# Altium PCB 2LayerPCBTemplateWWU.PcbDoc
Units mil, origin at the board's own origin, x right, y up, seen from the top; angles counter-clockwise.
Board outline 4800 x 1750 mil, 2 copper layers (Top Layer, Bottom Layer); 87 components, 55 nets, 244 pads, 65 vias.
Unrouted connection lines stored in the file: 2.
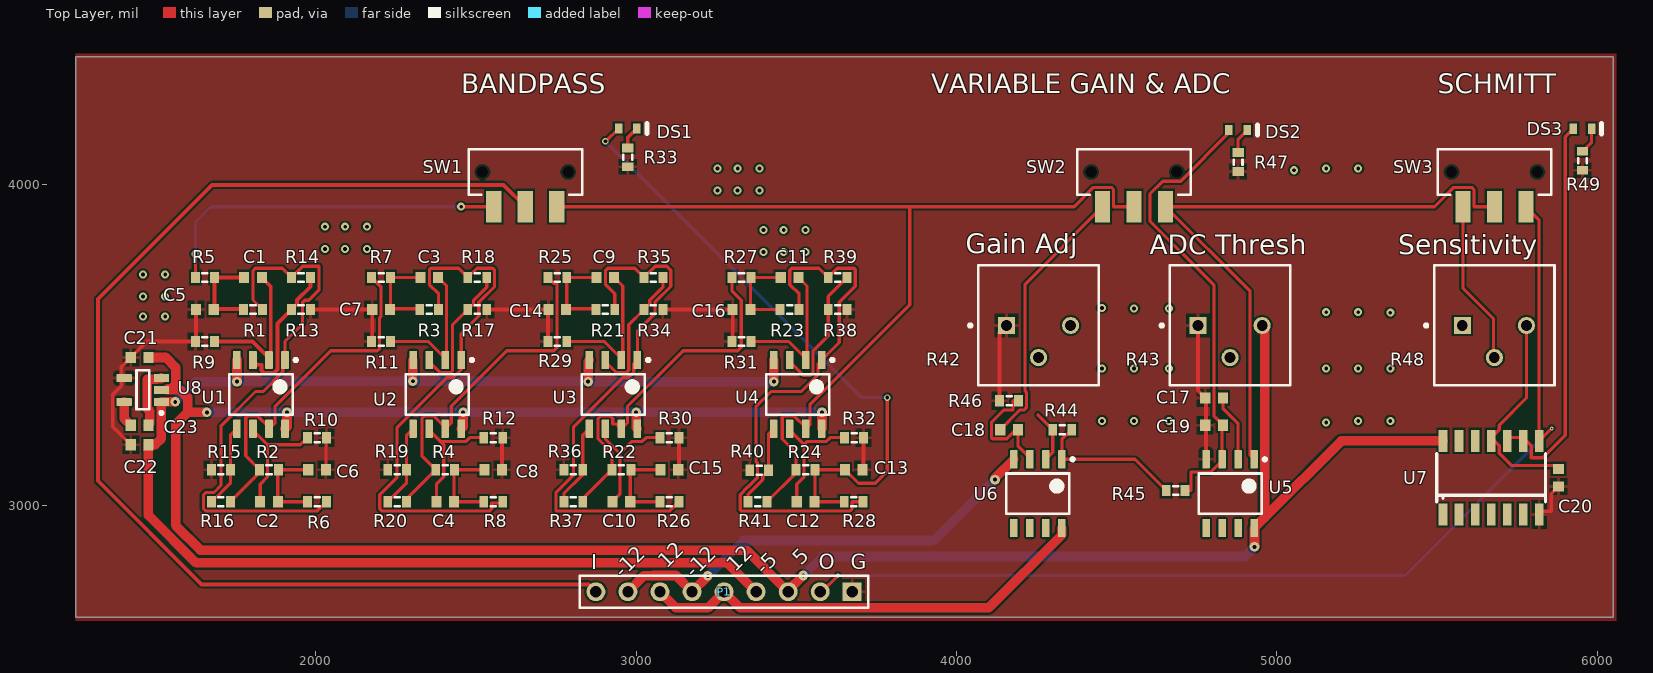
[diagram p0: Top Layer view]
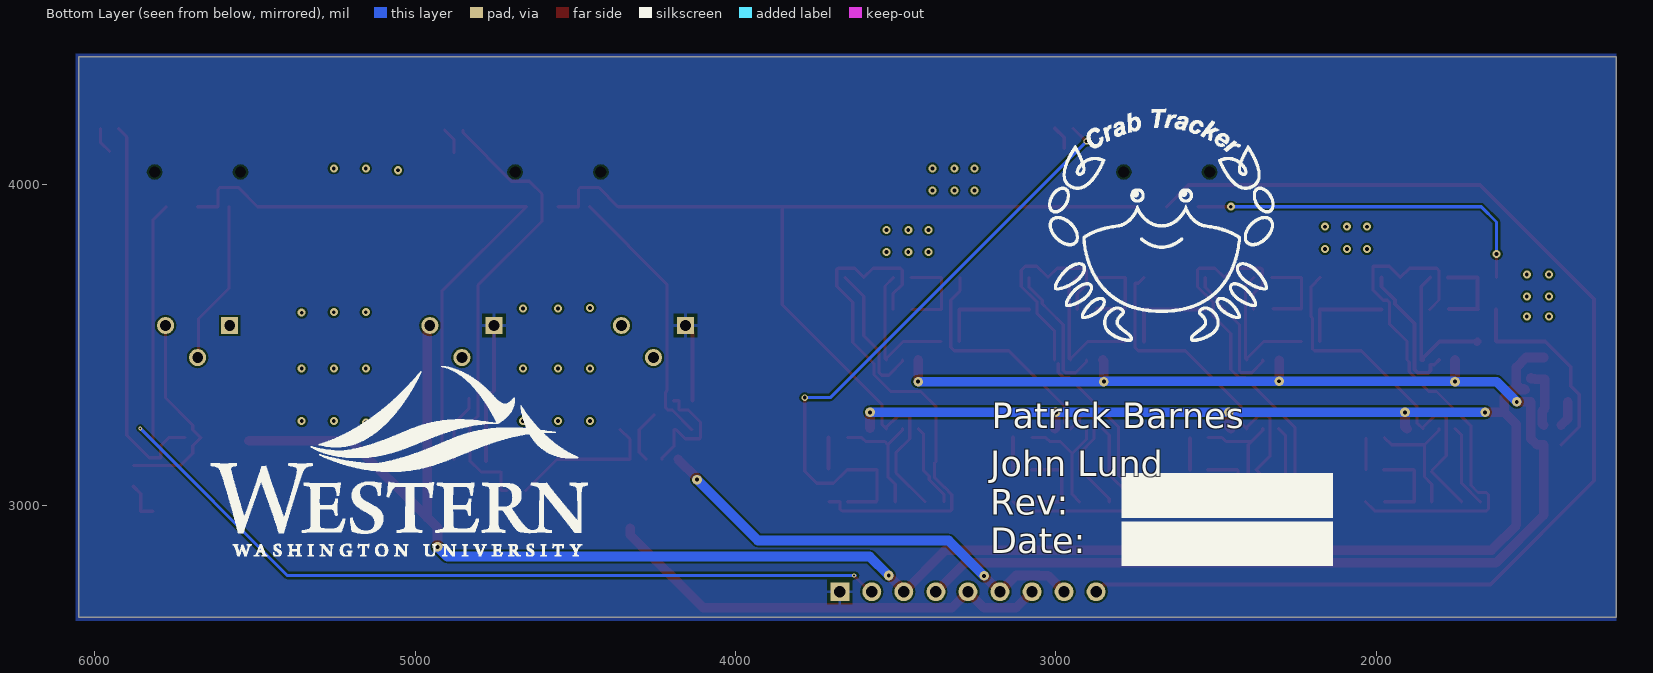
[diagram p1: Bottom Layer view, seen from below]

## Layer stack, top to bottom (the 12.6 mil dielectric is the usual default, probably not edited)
Top Solder: solder mask 0.4, Solder Resist, Dk 3.5
Top Layer: signal copper 1.4
Dielectric 1: dielectric 12.6, FR-4, Dk 4.8
Bottom Layer: signal copper 1.4
Bottom Solder: solder mask 0.4, Solder Resist, Dk 3.5

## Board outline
1250,2650 6050,2650 6050,4400 1250,4400

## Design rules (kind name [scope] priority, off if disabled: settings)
Clearance [All] p1: gap=6 ignorepadtopadclearanceinfootprint=FALSE except(0: Arc-Hole Track-Hole SMDPad-Hole THPad-Hole Via-Hole Fill-Hole Poly-Hole Region-Hole Text-Hole)
HoleSize [All] p1: absolutevalues=TRUE maxlimit=125 minlimit=13 maxpercent=80.000 minpercent=20.000
MinimumSolderMaskSliver [All] p1: minsoldermaskwidth=1
PasteMaskExpansion [All] p1: expansion=-2
PolygonConnect [All] p1: connectstyle=Relief reliefconductorwidth=10 reliefentries=4 polygonreliefangle="90 Angle" airgapwidth=10
RoutingVias [All] p1: holewidth=13 width=20 viastyle="Through Hole" minholewidth=13 minwidth=20 maxholewidth=125 maxwidth=250
SilkToSilkClearance [All] p1: silktosilkclearance=4
SilkToSolderMaskClearance [IsPad] p1: minsilkscreentomaskgap=6 clearancetoexposedcopper=TRUE
SolderMaskExpansion [All] p1: expansion=4
Width [All] p1: maxlimit=500 minlimit=6 preferedwidth=25
25 further rules are at their usual default settings.

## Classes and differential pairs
component class SchmittTrigger: C20 DS3 R48 R49 SW3 U7
component class BandpassFilter: C1 C2 C3 C4 C5 C6 C7 C8 C9 C10 C11 C12 C13 C14 C15 C16 C21 C22 C23 DS1 P1 R1 R2 R3 R4 R5 R6 R7 R8 R9 R10 R11 R12 R13 R14 R15 R16 R17 R18 R19 R20 R21 R22 R23 R24 R25 R26 R27 R28 R29 R30 R31 R32 R33 R34 R35 R36 R37 R38 R39 R40 R41 SW1 U1 U2 U3 U4 U8
component class ADC: C17 C18 C19 DS2 R42 R43 R44 R45 R46 R47 SW2 U5 U6

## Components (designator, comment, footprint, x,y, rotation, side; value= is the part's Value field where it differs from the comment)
C1 "Cap Semi" 1608[0603] 1803.91,3711.04 r0 top value=10nF
C2 "Cap Semi" 1608[0603] 1853.91,3011.04 r180 top value=10nF
C3 "Cap Semi" 1608[0603] 2353.91,3711.04 r0 top value=10nF
C4 "Cap Semi" 1608[0603] 2403.91,3011.04 r180 top value=10nF
C5 "Cap Semi" 1608[0603] 1653.91,3611.04 r0 top value=10nF
C6 "Cap Semi" 1608[0603] 2003.91,3111.04 r180 top value=10nF
C7 "Cap Semi" 1608[0603] 2203.91,3611.04 r0 top value=10nF
C8 "Cap Semi" 1608[0603] 2553.91,3111.04 r180 top value=10nF
C9 "Cap Semi" 1608[0603] 2903.91,3711.04 r0 top value=10nF
C10 "Cap Semi" 1608[0603] 2953.91,3011.04 r180 top value=10nF
C11 "Cap Semi" 1608[0603] 3478.91,3711.04 r0 top value=10nF
C12 "Cap Semi" 1608[0603] 3528.91,3011.04 r180 top value=10nF
C13 "Cap Semi" 1608[0603] 3678.91,3111.04 r180 top value=10nF
C14 "Cap Semi" 1608[0603] 2753.91,3611.04 r0 top value=10nF
C15 "Cap Semi" 1608[0603] 3103.91,3111.04 r180 top value=10nF
C16 "Cap Semi" 1608[0603] 3328.91,3611.04 r0 top value=10nF
C17 "Cap Semi" 1608[0603] 4803.91,3334.82 r180 top value=1uF
C18 "Cap Semi" 1608[0603] 4163.91,3236.04 r0 top value=0.1uF
C19 "Cap Semi" 1608[0603] 4803.91,3250.04 r0 top value=10nF
C20 "Cap Semi" 1608[0603] 5878.91,3086.04 r270 top value=10nF
C21 "Cap Semi" 1608[0603] 1450,3461.04 r0 top value=1uF
C22 "Cap Semi" 1608[0603] 1450,3188.77 r0 top value=1uF
C23 "Cap Semi" 1608[0603] 1450,3250 r0 top value=1uF
DS1 "TLMS1100-GS08" VISH-TLMX1100_V 2973.91,4176.04 r0 top
DS2 "TLMS1100-GS08" VISH-TLMX1100_V 4878.91,4171.04 r0 top
DS3 "TLMS1100-GS08" VISH-TLMX1100_V 5953.91,4175.17 r0 top
P1 "Header 9" HDR1X9 3674.38,2730 r180 top
R1 "Res3" J1-0603 1803.91,3611.04 r0 top value=220
R2 "Res3" J1-0603 1853.91,3111.04 r180 top value=220
R3 "Res3" J1-0603 2353.91,3611.04 r0 top value=220
R4 "Res3" J1-0603 2403.91,3111.04 r180 top value=220
R5 "Res3" J1-0603 1653.91,3711.04 r0 top value=100k
R6 "Res3" J1-0603 2003.91,3011.04 r180 top value=68k
R7 "Res3" J1-0603 2203.91,3711.04 r0 top value=100k
R8 "Res3" J1-0603 2553.91,3011.04 r180 top value=68k
R9 "Res3" J1-0603 1653.91,3511.04 r0 top value=330
R10 "Res3" J1-0603 2003.91,3211.04 r180 top value=330
R11 "Res3" J1-0603 2203.91,3511.04 r0 top value=330
R12 "Res3" J1-0603 2553.91,3211.04 r180 top value=330
R13 "Res3" J1-0603 1953.91,3611.04 r180 top value=470
R14 "Res3" J1-0603 1953.91,3711.04 r180 top value=1k
R15 "Res3" J1-0603 1703.91,3111.04 r0 top value=1k
R16 "Res3" J1-0603 1703.91,3011.04 r0 top value=1k
R17 "Res3" J1-0603 2503.91,3611.04 r180 top value=470
R18 "Res3" J1-0603 2503.91,3711.04 r180 top value=1k
R19 "Res3" J1-0603 2253.91,3111.04 r0 top value=1k
R20 "Res3" J1-0603 2253.91,3011.04 r0 top value=1k
R21 "Res3" J1-0603 2903.91,3611.04 r0 top value=220
R22 "Res3" J1-0603 2953.91,3111.04 r180 top value=220
R23 "Res3" J1-0603 3478.91,3611.04 r0 top value=220
R24 "Res3" J1-0603 3528.91,3111.04 r180 top value=220
R25 "Res3" J1-0603 2753.91,3711.04 r0 top value=100k
R26 "Res3" J1-0603 3103.91,3011.04 r180 top value=68k
R27 "Res3" J1-0603 3328.91,3711.04 r0 top value=100k
R28 "Res3" J1-0603 3678.91,3011.04 r180 top value=68k
R29 "Res3" J1-0603 2753.91,3511.04 r0 top value=330
R30 "Res3" J1-0603 3103.91,3211.04 r180 top value=330
R31 "Res3" J1-0603 3328.91,3511.04 r0 top value=330
R32 "Res3" J1-0603 3680.19,3211.04 r180 top value=330
R33 "Res3" J1-0603 2973.91,4086.04 r90 top value=1K
R34 "Res3" J1-0603 3053.91,3611.04 r180 top value=470
R35 "Res3" J1-0603 3053.91,3711.04 r180 top value=1k
R36 "Res3" J1-0603 2803.91,3111.04 r0 top value=1k
R37 "Res3" J1-0603 2803.91,3011.04 r0 top value=1k
R38 "Res3" J1-0603 3628.91,3611.04 r180 top value=470
R39 "Res3" J1-0603 3628.91,3711.04 r180 top value=1k
R40 "Res3" J1-0603 3383.91,3109.07 r0 top value=1k
R41 "Res3" J1-0603 3378.91,3011.04 r0 top value=1k
R42 "3386P-1-104LF" BOUR-3386P 4256.03,3511.04 r0 top
R43 "3386P-1-104LF" BOUR-3386P 4853.91,3511.04 r0 top
R44 "Res3" J1-0603 4330.05,3236.04 r180 top value=20k
R45 "Res3" J1-0603 4683.91,3046.04 r0 top value=5k
R46 "Res3" J1-0603 4163.91,3326.04 r0 top value=1M
R47 "Res3" J1-0603 4878.91,4071.04 r90 top value=1k
R48 "3386P-1-104LF" BOUR-3386P 5678.91,3511.04 r0 top
R49 "Res3" J1-0603 5953.91,4075.17 r270 top value=1k
SW1 "JS102011SAQN" CKCP-JS102011SAQN-3_V 2653.91,3986.04 r180 top
SW2 "JS102011SAQN" CKCP-JS102011SAQN-3_V 4553.91,3986.04 r180 top
SW3 "JS102011SAQN" CKCP-JS102011SAQN-3_V 5678.91,3986.04 r180 top
U1 "OPA2171AIDR" D0008A_N 1828.91,3346.04 r270 top
U2 "OPA2171AIDR" D0008A_N 2378.91,3346.04 r270 top
U3 "OPA2171AIDR" D0008A_N 2928.91,3346.04 r270 top
U4 "OPA2171AIDR" D0008A_N 3503.91,3346.04 r270 top
U5 "OPA2171AIDR" D0008A_N 4853.91,3036.04 r270 top
U6 "OPA2171AIDR" D0008A_N 4253.91,3036.04 r270 top
U7 "74HC14D HEX INV" 14-SOIC 5668.91,3086.04 r0 top
U8 "TPS60403DBVR" DBV0005A_M 1460,3360 r180 top

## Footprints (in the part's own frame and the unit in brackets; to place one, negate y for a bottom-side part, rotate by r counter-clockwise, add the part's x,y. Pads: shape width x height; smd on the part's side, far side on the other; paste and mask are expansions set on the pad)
14-SOIC [mm] "14-SOIC 74HC14"
  rect 0.7x1.75 smd: 1(-3.81,-2.921) 2(-2.54,-2.921) 3(-1.27,-2.921) 4(0,-2.921) 5(1.27,-2.921) 6(2.54,-2.921) 7(3.81,-2.921) 8(3.81,2.921) 9(2.54,2.921) 10(1.27,2.921) 11(0,2.921) 12(-1.27,2.921) 13(-2.54,2.921) 14(-3.81,2.921)
  silkscreen extent -4.32,-1.91 4.32,1.91, body extent -4.32,-2.92 4.32,2.92, height 1.6
1608[0603] [mm] "Chip Capacitor, Body 1.6x0.8mm, IPC High Density"
  rect 0.8x0.9 smd: 1(-0.7,0) 2(0.7,0)
  body extent -0.87,-0.48 0.87,0.48, height 1.3
BOUR-3386P [mm] "THD, 3-Leads, Body 9.53x9.53mm, Pitch 2.54mm"
  rect 1.35x1.35 hole 0.85: 1(-2.54,1.27)
  round 1.35 hole 0.85: 2(0,-1.27) 3(2.54,1.27)
  silkscreen extent -5.54,-3.48 4.76,6.05, body extent -4.79,-3.52 4.79,6.06, height 4.95
CKCP-JS102011SAQN-3_V [mm] "SMD, 3-Leads, Body 9x3.6mm, Pitch 2.5mm"
  rect 1.2x2.5 smd: 1(-2.5,1.375) 2(0,1.375) 3(2.5,1.375)
  round 0.6 hole 0.9 unplated: MH1(-3.4,-1.375) MH2(3.4,-1.375)
  silkscreen extent -4.5,-3.17 4.5,0.43, body extent -4.5,-5.18 4.5,2.37, height 3.52
D0008A_N [mm] "SOIC, 8-Leads, Body 5x4mm, Pitch 1.27mm, IPC Medium Density"
  rrect17% 1.45x0.6 smd: 1(-2.725,1.905) 2(-2.725,0.635) 3(-2.725,-0.635) 4(-2.725,-1.905) 5(2.725,-1.905) 6(2.725,-0.635) 7(2.725,0.635) 8(2.725,1.905)
  silkscreen extent -2.85,-2.5 1.6,2.88, body extent -3,-2.45 3,2.45, height 1.63
DBV0005A_M [mm] "SOT23, 5-Leads, Body 3.05x1.75mm, Pitch 0.95mm, IPC Low Density"
  rrect15% 1.2x0.65 smd: 1(-1.475,0.95) 2(-1.475,0) 3(-1.475,-0.95) 4(1.475,-0.95) 5(1.475,0.95)
  silkscreen extent -1.6,-1.55 0.5,1.95, body extent -1.42,-1.46 1.42,1.46, height 1.08
HDR1X9 [mm] "Connector; Header; 9 Position"
  rect 1.5x1.5 hole 0.9: 1(0,0)
  round 1.5 hole 0.9: 2(2.54,0) 3(5.08,0) 4(7.62,0) 5(10.16,0) 6(12.7,0) 7(15.24,0) 8(17.78,0) 9(20.32,0)
  silkscreen extent -1.27,-1.27 21.59,1.27
J1-0603 [mm] "Chip Resistor, Body 1.6x0.8mm, IPC High Density"
  rect 0.7x0.9 smd: 1(-0.75,0) 2(0.75,0)
  silkscreen extent -0.2,-0.35 0.2,0.35, body extent -0.85,-0.48 0.85,0.48, height 0.9
VISH-TLMX1100_V [mm] "SMD, 2-Leads, Body 1.6x0.8mm"
  rect 0.6x0.8 smd: 1(-0.725,0) 2(0.725,0)
  silkscreen extent 1.53,-0.4 1.53,0.4, body extent -0.8,-0.4 0.8,0.4, height 0.65

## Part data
C1 C2 C3 C4 C5 C6 C7 C8 C9 C10 C11 C12 C13 C14 C15 C16 C17 C18 C19 C20 C21 C22 C23: "Capacitor (Semiconductor SIM Model)"
DS1 DS2 DS3: library part CMP-1666-00027-1, "LED, RED, 2.1 V, -40 to 100 degC, 2-Pin SMD (0603), RoHS, Tape and Reel", Capacitance="12 pF", Case/Package=0603, Case Code (Metric)=1608, Max Operating Temperature=125degC, Min Operating Temperature=-55degC, Package Quantity=4000, Resistance="100000000000 Ohm", Tolerance=5%, Type (Capacitors)=C0G, Voltage Rating="50 V"
P1: "Header, 9-Pin"
R1 R2 R3 R4 R5 R6 R7 R8 R9 R10 R11 R12 R13 R14 R15 R16 R17 R18 R19 R20 R21 R22 R23 R24 R25 R26 R27 R28 R29 R30 R31 R32 R33 R34 R35 R36 R37 R38 R39 R40 R41 R44 R45 R46 R47 R49: "Resistor"
R42 R43 R48: library part CMP-2000-05592-1, "Square Trimpot(R) Trimming Potentiometer, 100 KOhm, +/- 10%, 0.5 W, -55 to 125 degC, 3-Pin THD, RoHS, Tube", Manufacturer=Bourns, Manufacturer Series=3386, Maximum Operating Temperature=125C, Minimum Operating Temperature=-55C, Operating Temperature-Max (Cel)=125, Operating Temperature-Min (Cel)=-55, Package=RectangularPackage, Package Description="3-Pin Through Hole Device, Body 9.53 x 9.53 mm, Pitch 2.54 mm", Package Reference=3386P, Power Rating=1/2W, Rated Power Dissipation (P) (W)=0.5, Rated Temperature (Cel)=85, Resistance (ohm)=100000, Resistance Law=Linear, Resistance Value=100KOhm, Resistive Element Material=Cermet, Temperature Coefficient=100ppm/C, Tolerance=10%, Tolerance (%)=10
SW1 SW2 SW3: library part CMP-2000-06501-1, "Sub-Miniature Slide Switch, SPDT, -40 to 85 degC, 3-Pin SMD, RoHS, Tape and Reel", Actuator Color=Black, Contact Rating @ Voltage=0.3@6VDCA, Dielectric Strength=500VAC, Manufacturer="C&K Components", Maximum AC Voltage Rating=N/A, Maximum Contact Resistance=70mOhm, Maximum DC Voltage Rating=6V, Minimum Insulation Resistance=100MOhm, Operating Temperature=-40to85C, Package Description="3-Pin Surface Mount Device, Body 9 x 3.6 mm, Height 3.5 mm", Package Reference=SMT
U1 U2 U3 U4 U5 U6: library part CMP-0272-00237-3, "Low Power, RRO, General Purpose Operational Amplifier in MicroPackage, 2.7 to 36 V, -40 to 125 degC, 8-pin SOIC (D8), Green (RoHS & no Sb/Br)", Manufacturer="Texas Instruments", Rating=Catalog, Total Supply Voltage(Max)(+5V is 5, +/-5V is 10)=36, Total Supply Voltage(Min)(+5V is 5, +/-5V is 10)=2.7
U7: library part "SCHMITT INVERTER 6INV 74HC14", "74HC14D Schmitt triggered inverter", Supplier Part Number 1=568-3953-5-ND
U8: library part CMP-0391-00006-2, "-1.8 to -5.25 V, Inverting Charge Pump Regulator, 60 mA, 1.8 to 5.25 V Input with 2-Cell Alkaline / Nixx Input, -40 to 85 degC, 5-pin SOT23 (DBV5), Green (RoHS & no Sb/Br)", Manufacturer="Texas Instruments", Switching Frequency(Max)(kHz)=300

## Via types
v1: diameter 25, hole 12, Top Layer to Bottom Layer, tented both sides, 47 vias
v2: diameter 30, hole 12, Top Layer to Bottom Layer, tented both sides, 14 vias
v3: diameter 12, hole 6, Top Layer to Bottom Layer, tented both sides, 2 vias
v4: diameter 20, hole 12, Top Layer to Bottom Layer, tented both sides, 2 vias

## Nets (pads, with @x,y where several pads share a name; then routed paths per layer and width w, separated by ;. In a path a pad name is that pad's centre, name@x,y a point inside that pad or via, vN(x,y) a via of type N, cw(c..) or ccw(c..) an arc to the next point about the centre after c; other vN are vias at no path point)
GND: C5.1 C6.1 C7.1 C8.1 C13.1 C14.1 C15.1 C16.1 C17.2 C19.1 C20.2 C21.1 C22.1 P1.1 R9.1 R10.1 R11.1 R12.1 R13.1 R15.1 R17.1 R19.1 R29.1 R30.1 R31.1 R32.1 R33.1 R34.1 R36.1 R38.1 R40.1 R42.1 R43.1 R46.1 R47.1 R49.2 U5.4 U7.7 U8.4 | length 2733.4
  Top Layer w10: C6.1 R10.1@2031.46,3209.07
  Top Layer w12: C22.1 1366.31,3244.9 1366.31,3345.24 1392.93,3371.86 1392.93,3431.53 C21.1 1472.44,3511.04 R9.1 ; R9.1@1626.35,3513.01 C5.1 ; R13.1 C7.1 R11.1@2176.35,3513.01 ; R17.1 C14.1 2724.38,3609.07 R29.1 ; C8.1 R12.1@2581.46,3209.07 ; R34.1 C16.1 R31.1@3301.35,3513.01 ; C15.1@3133.43,3113.01 R30.1 ; C13.1@3709.72,3114.29 R32.1 ; R46.1 4134.38,3539.38 R42.1 ; R43.1 4753.91,3357.26 C17.2 4778.91,3332.26 U5.4 U5.4@4778.91,3137.17 ; U7.7@5818.91,2981.04 5856.46,2981.04 5856.46,3036.04 C20.2
NetC1_1: C1.1 C5.2 R1.1 R5.2 | length 282.7
  Top Layer w10: C5.2 C5.2@1683.43,3613.01
  Top Layer w12: R1.1@1772.41,3613.01 1683.43,3613.01 R5.2 C1.1
NetC1_2: C1.2 R9.2 U1.2 | length 474.3
  Top Layer w12: R9.2 1802.34,3511.04 1853.91,3459.47 U1.2 1859.21,3453.32 1859.21,3683.29 C1.2
  Top Layer w25: R9.2 R9.2@1684.71,3509.76
NetC2_1: C2.1 C6.2 R2.1 R6.2 | length 286.6
  Top Layer w10: R6.2 C2.1 1881.46,3109.07 R2.1 C6.2
NetC2_2: C2.2 R10.2 U1.6 | length 390.4
  Top Layer w10: U1.6 1803.91,3234.02 1849.16,3188.77 ; C2.2 1826.35,3065.96 1849.16,3088.77 1849.16,3188.77 ; R10.2 1952.11,3188.77 1849.16,3188.77
NetC3_1: C3.1 C7.2 R3.1 R7.2 | length 279.9
  Top Layer w10: R3.1@2322.41,3613.01 2233.43,3613.01 R7.2 C3.1
NetC3_2: C3.2 R11.2 U2.2 | length 467.7
  Top Layer w10: R11.2 2350.92,3511.04 2403.91,3458.06 U2.2 2408.21,3457.63 2408.21,3684.29 C3.2
NetC4_1: C4.1 C8.2 R4.1 R8.2 | length 286.6
  Top Layer w10: R8.2 C4.1 2431.46,3109.07 R4.1 C8.2
NetC4_2: C4.2 R12.2 U2.6 | length 396.5
  Top Layer w10: U2.6 2353.91,3234.02 2388.71,3199.21 ; C4.2 2376.35,3065.96 2399.16,3088.77 2399.16,3188.77 2388.71,3199.21 ; R12.2 2480.92,3211.04 2469.1,3199.21 2388.71,3199.21
NetC9_1: C9.1 C14.2 R21.1 R25.2 | length 279.9
  Top Layer w10: R21.1@2872.41,3613.01 2783.43,3613.01 R25.2 C9.1
NetC9_2: C9.2 R29.2 U3.2 | length 467.7
  Top Layer w10: R29.2 2900.92,3511.04 2953.91,3458.06 U3.2 2958.21,3457.63 2958.21,3684.29 C9.2
NetC10_1: C10.1 C15.2 R22.1 R26.2 | length 286.6
  Top Layer w10: R26.2 C10.1 2981.46,3109.07 R22.1 C15.2
NetC10_2: C10.2 R30.2 U3.6 | length 401.7
  Top Layer w10: U3.6 2903.91,3206.65 2949.16,3161.4 ; C10.2 2949.16,3033.85 2949.16,3161.4 ; R30.2 3030.92,3211.04 3019.1,3199.21 2986.97,3199.21 2949.16,3161.4
NetC11_1: C11.1 C16.2 R23.1 R27.2 | length 286.6
  Top Layer w10: R23.1 C16.2 3356.46,3709.07 R27.2 C11.1
NetC11_2: C11.2 R31.2 U4.2 | length 467.7
  Top Layer w10: R31.2 3475.92,3511.04 3528.91,3458.06 U4.2 3533.21,3457.63 3533.21,3684.29 C11.2
NetC12_1: C12.1 C13.2 DS1.1 R24.1 R28.2 | length 1947.8
  Top Layer w10: v4(2903.91,4136.04) 2905.36,4136.04 DS1.1 ; R28.2 3560.4,3011.04 3558.43,3013.01 R24.1 C13.2 3693.91,3068.48 3746.35,3068.48 3783.91,3106.04 v4(3783.91,3336.04)
  Bottom Layer w10: v4(2903.91,4136.04) 3703.91,3336.04 v4(3783.91,3336.04)
NetC12_2: C12.2 R32.2 U4.6 | length 391.6
  Top Layer w10: U4.6 3478.91,3234.02 3524.16,3188.77 ; C12.2 3501.35,3065.96 3524.16,3088.77 3524.16,3188.77 ; R32.2 3605.92,3211.04 3594.1,3199.21 3534.6,3199.21 3524.16,3188.77
NetC17_1: C17.1 R43.2 U5.2 | length 211.2
  Top Layer w10: C17.1 4831.46,3302.24 4878.91,3254.8 U5.2
NetC18_1: C18.1 SW2.3 | length 839.9
  Top Layer w10: C18.1 4197.63,3297.32 4211.77,3297.32 4218.21,3303.77 4218.21,3352.62 4213.91,3356.93 4213.91,3690.33 SW2.3
NetC18_2: C18.2 R46.2 U6.3 | length 380.7
  Top Layer w10: R46.2 4175.83,3326.04 4175.83,3298.16 4175,3297.32 4147.12,3297.32 4109.6,3259.8 4109.6,3209.68 4111.95,3207.32 4156.65,3207.32 4185.37,3236.04 C18.2 4191.46,3185.5 4228.91,3148.06 U6.3
NetC19_2: C19.2 DS2.1 R45.2 U5.3 | length 1446.2
  Top Layer w10: R45.2 4731.62,3046.04 4731.62,3102.8 4732.61,3103.78 4794.1,3103.78 4828.91,3138.59 U5.3 C19.2@4828.91,3247.49 ; C19.2 4803.91,3277.6 4803.91,3686.04 4603.91,3886.04 4603.91,3971.87 4643.49,4011.46 4699.66,4011.46 4850.36,4162.16 DS2.1
NetC20_1: C20.1 R48.3 U7.11 | length 655.7
  Top Layer w10: R48.3 5778.91,3334.82 5694.13,3250.04 5694.13,3236.26 5668.91,3211.04 5694.13,3185.82 5694.13,3162.03 5732.56,3123.6 C20.1@5878.91,3123.6
NetC21_2: C21.2 P1.3 R43.3 U1.8 U2.8 U3.8 U4.8 U5.8 U7.14 U8.2 | length 7749.5
  Top Layer w30: C21.2 1532.24,3461.04 1562.69,3430.58 1562.69,3377.03 1549.27,3363.61 1537.99,3363.61 1534.38,3360 1576.24,3360 1600,3336.24 1600,3290 ; v2(1660,3290) 1600,3290 ; U1.8 1910,3244.85 v2(1910,3290) ; U2.8 2460,3244.85 v2(2460,3290) ; v2(3000,3290) 3000,3242.66 U3.8 ; v2(3521.53,2780.53) 3474.38,2733.38 P1.3 3344.38,2860 1640,2860 1562.69,2937.31 1562.69,3252.69 1600,3290 ; U4.8@3580,3239.85 v2(3580,3290) ; v2(4930,2870) 4930,2927.66 U5.8 4961.72,2961.57 ; R43.3 4961.72,3561.04 4961.72,2961.57 ; U7.14 5201.19,3201.04 4961.72,2961.57
  Bottom Layer w30: v2(1660,3290) v2(1910,3290) v2(2460,3290) v2(3000,3290) v2(3580,3290) ; v2(3521.53,2780.53) 3581,2840 4900,2840 v2(4930,2870)
NetC22_2: C22.2 P1.4 U1.4 U2.4 U3.4 U4.4 U8.1 | length 4587.2
  Top Layer w30: v2(1561.07,3322.6) U8.1 1518.07,3208.07 1498.77,3188.77 C22.2 1477.56,2968.68 1626.24,2820 3284.38,2820 P1.4 ; v2(1753.91,3386.04) U1.4 ; v2(2303,3387) U2.4@2303,3452.42 ; v2(2850,3386.04) 2850,3449.42 U3.4 ; U4.4 3430.04,3452.19 v2(3430.04,3386.04)
  Bottom Layer w30: v2(1561.07,3322.6) 1624.51,3386.04 v2(1753.91,3386.04) 1754.87,3387 v2(2303,3387) 2849.04,3387 v2(2850,3386.04) v2(3430.04,3386.04)
NetC23_1: C23.1 U8.5 | length 81.1
  Top Layer w30: U8.5 1401.93,3270.51 C23.1
NetC23_2: C23.2 U8.3 | length 197
  Top Layer w30: C23.2 1482.07,3254.51 1482.07,3293.61 1473.45,3302.23 1473.45,3393.8 1503.76,3393.8 1504.56,3394.6 1518.07,3394.6 U8.3
NetDS1_2: DS1.2 R33.2 | length 72.3
  Top Layer w12: R33.2 2973.91,4147.5 DS1.2
NetDS2_2: DS2.2 R47.2 | length 82.3
  Top Layer w10: R47.2 4878.9,4142.5 DS2.2
NetDS3_1: DS3.1 U7.9 U7.10 | length 1225.7
  Top Layer w10: U7.10@5718.91,3211.04 5768.91,3211.04 5794.13,3185.82 5794.13,3148.06 5829.71,3148.06 5900,3218.35 5900,4149.81 DS3.1
NetDS3_2: DS3.2 R49.1 | length 82.3
  Top Layer w10: R49.1 5982.45,4133.24 DS3.2
NetP1_2: P1.2 SW3.1 U7.8 | length 3303
  Top Layer w10: P1.2 3579.47,2730 v3(3630,2780.53) ; SW3.1 5817.91,3891.33 5817.91,3202.04 U7.8 v3(5857.87,3240)
  Bottom Layer w10: v3@3624.91,2780.53 v3(3630,2780.53) 5398.39,2780.53 v3(5857.87,3240)
NetP1_5: P1.5 P1.7 U6.8 | length 1432.8
  Top Layer w30: P1.7 3124.38,2680 3152.92,2680 3153.45,2679.47 3223.85,2679.47 P1.5 3324.91,2679.47 4100.47,2679.47 4328.91,2907.91 U6.8
NetP1_6: P1.6 P1.8 U6.4 | length 1420.2
  Top Layer w30: P1.8 3024.38,2780 3052.92,2780 3053.45,2780.53 3123.85,2780.53 P1.6 v2(3223.85,2779.47) ; v2(4120,3080) 4120,3084.42 U6.4
  Bottom Layer w30: v2(3223.85,2779.47) 3334.38,2890 3930,2890 v2(4120,3080)
NetR1_2: R1.2 R6.1 R14.2 U1.1 | length 1711.3
  Top Layer w10: R1.2 1803.91,3640.57 1803.91,3732.5 1811.16,3739.76 1895.66,3739.76 R14.2 1959.38,3746.04 2010.37,3746.04 2010.37,3672.5 1977.62,3639.76 1965.1,3639.76 1958.65,3633.31 1958.65,3566.04 1903.91,3511.29 U1.1 1897.09,3446.51 1897.09,3416.32 1835.81,3355.04 1811.88,3355.04 1703.91,3247.06 1703.91,3061.51 1682.15,3039.76 1656.04,3039.76 1649.6,3033.31 1649.6,2988.77 1656.04,2982.32 2004.72,2982.32 R6.1
NetR2_2: R2.2 R7.1 R16.2 U1.7 | length 1120.8
  Top Layer w10: R16.2 R2.2@1826.72,3104.32 ; R2.2 1781.09,3154.32 1781.09,3273.49 1785.9,3278.3 1819.1,3278.3 1853.91,3243.49 U1.7 1872.91,3257.76 1872.91,3308.88 2046.35,3482.32 2192.71,3482.32 2199.16,3488.77 2199.16,3584.83 2203.09,3588.77 2203.09,3682.32 R7.1
NetR3_2: R3.2 R8.1 R18.2 U2.1 | length 1681.8
  Top Layer w10: R3.2 2383.43,3660.05 2354.72,3688.77 2354.72,3735.23 2359.24,3739.76 2445.66,3739.76 R18.2 2503.09,3739.76 2551.77,3739.76 2558.21,3733.31 2558.21,3682.87 2508.65,3633.31 2508.65,3590.79 2453.91,3536.04 U2.1 2453.91,3423.69 2427.99,3397.78 2408.19,3397.78 2253.91,3243.49 2253.91,3087.62 2199.6,3033.31 2199.6,2988.77 2206.04,2982.32 2542.71,2982.32 2549.16,2988.77 2549.16,3007.23 2579.62,3007.23 R8.1
NetR4_2: R4.2 R20.2 R25.1 U2.7 | length 1131
  Top Layer w10: R20.2 2283.43,3020.09 R4.2 2331.09,3154.32 2331.09,3270.68 2338.71,3278.3 2369.1,3278.3 2403.91,3243.49 U2.7 2422.91,3257.76 2422.91,3308.88 2596.35,3482.32 2742.71,3482.32 2753.09,3492.7 2753.09,3692.7 2742.71,3692.7 R25.1
NetR5_1: R5.1 SW1.3 | length 1123.9
  Top Layer w10: R5.1 v1(1624.38,3784.07) ; v1(2453.91,3931.91) SW1.3
  Bottom Layer w10: v1(1624.38,3784.07) 1624.38,3884.07 1672.21,3931.91 v1(2453.91,3931.91)
NetR13_2: R13.2 R14.1 U1.3 | length 438.1
  Top Layer w12: U1.3 1818.81,3438.42 1830.09,3438.42 1830.09,3420.99 1838.3,3412.78 1869.51,3412.78 1880.09,3423.36 1880.09,3566.76 R13.2 1941.65,3628.31 1941.65,3640.35 1983.43,3682.13 R14.1
NetR15_2: R15.2 R16.1 U1.5 | length 261.6
  Top Layer w10: R16.1 1676.06,3011.04 1733.43,3068.41 R15.2 1733.43,3218.28 U1.5
NetR17_2: R17.2 R18.1 U2.3 | length 430.3
  Top Layer w10: U2.3 2353.91,3448.59 2388.71,3413.78 2421.36,3413.78 2426.72,3419.13 2426.72,3563.38 R17.2 2492.65,3629.31 2492.65,3639.94 2533.43,3680.72 R18.1
NetR19_2: R19.2 R20.1 U2.5 | length 260.7
  Top Layer w10: R20.1 2283.43,3070.09 R19.2 2283.43,3218.28 U2.5
NetR21_2: R21.2 R26.1 R35.2 U3.1 | length 1661.7
  Top Layer w10: R21.2 2933.43,3660.05 2904.72,3688.77 2904.72,3733.31 2911.16,3739.76 2995.66,3739.76 R35.2 3059.38,3746.04 3095.49,3746.04 3108.21,3733.31 3108.21,3682.87 3058.65,3633.31 3058.65,3598.26 3003.91,3543.51 U3.1 ; U3.1@2992.72,3442.13 2992.72,3414.77 2975.72,3397.78 2958.19,3397.78 2804.17,3243.76 2804.17,3093.78 2749.6,3039.21 2749.6,2982.32 3104.72,2982.32 R26.1
NetR22_2: R22.2 R27.1 R37.2 U3.7 | length 1157.3
  Top Layer w10: R37.2 2833.43,3020.09 R22.2 2924.38,3163.55 2881.09,3206.83 2881.09,3270.68 2888.71,3278.3 2919.1,3278.3 2926.72,3270.68 2926.72,3253.38 2939.28,3253.38 U3.7 2972.91,3257.76 2972.91,3308.88 3146.35,3482.32 3317.71,3482.32 3328.09,3492.7 3328.09,3639.76 3299.38,3668.47 R27.1
NetR23_2: R23.2 R28.1 R39.2 U4.1 | length 1736.4
  Top Layer w10: R23.2 3508.43,3660.05 3479.72,3688.77 3479.72,3733.95 3485.53,3739.76 3570.66,3739.76 R39.2 3628.09,3739.76 3680.19,3739.76 3683.91,3736.04 3683.91,3683.56 3633.65,3633.31 3633.65,3508.07 U4.1 3567.72,3442.13 3567.72,3407.15 3515.6,3355.04 3421.06,3355.04 3373.91,3307.88 3373.91,3136.6 3379.16,3131.34 3379.16,3086.8 3349.91,3057.56 3348.84,3057.56 3324.6,3033.31 3324.6,2985.82 3328.09,2982.32 3667.71,2982.32 3674.16,2988.77 3674.16,3011.04 R28.1
NetR24_2: R24.2 R41.2 SW1.1 SW2.2 U4.7 | length 3124.3
  Top Layer w10: SW1.1 3853.91,3931.91 ; R41.2 3499.38,3101.98 R24.2 3499.38,3163.55 3456.09,3206.83 3456.09,3276.11 3458.28,3278.3 3494.1,3278.3 3528.91,3243.49 U4.7 3542.91,3252.76 3542.91,3315.04 3853.91,3626.04 3853.91,3931.91 ; SW2.2 4490.1,3931.91 4490.1,3985.67 4483.66,3992.12 4427.3,3992.12 4367.09,3931.91 3853.91,3931.91
NetR34_2: R34.2 R35.1 U3.3 | length 429
  Top Layer w10: U3.3 2903.91,3448.59 2938.71,3413.78 2969.1,3413.78 2976.72,3421.4 2976.72,3563.38 R34.2 3042.65,3629.31 3042.65,3639.94 3083.43,3680.72 R35.1
NetR36_2: R36.2 R37.1 U3.5 | length 260.7
  Top Layer w10: R37.1 2774.38,3036.51 2833.43,3095.57 R36.2 2833.43,3218.28 U3.5
NetR38_2: R38.2 R39.1 U4.3 | length 439.9
  Top Layer w10: U4.3 3478.91,3448.59 3521.53,3405.97 3543.91,3405.97 3551.72,3413.78 3551.72,3480.87 3599.38,3528.53 R38.2 3599.38,3651.98 R39.1
NetR40_2: R40.2 R41.1 U4.5 | length 260.7
  Top Layer w10: R41.1 3349.38,3034.39 3395.16,3080.17 3395.16,3090.8 R40.2 3413.43,3223.28 U4.5
NetR42_2: R42.2 R44.2 U6.2 | length 167.6
  Top Layer w10: 4253.91,3282.65 R44.2 4300.52,3164.94 U6.2
NetR44_1: R44.1 R45.1 U6.1 | length 471.2
  Top Layer w10: R44.1 4328.91,3205.37 U6.1 4557.09,3143.32 R45.1
NetR48_2: R48.2 SW3.3 | length 511.6
  Top Layer w10: SW3.3 5580.48,3678.17 5675.75,3582.9 5675.75,3464.19 R48.2
NetSW2_1: SW2.1 SW3.2 U5.1 | length 2011.1
  Top Layer w10: U5.1 4916.33,3155.9 4916.33,3667.91 SW2.1 5492.09,3931.91 5552.3,3992.12 5608.66,3992.12 5615.1,3985.67 5615.1,3931.91 SW3.2
SIG_IN: P1.9 SW1.2 | length 3775
  Top Layer w12: SW1.2 2585.81,4000 1676.24,4000 1320,3643.76 1320,3076.24 1643.24,2753 2851.38,2753 P1.9
pads on no net: R42.3 R48.1 SW1.MH1 SW1.MH2 SW2.MH1 SW2.MH2 SW3.MH1 SW3.MH2 U5.5 U5.6 U5.7 U6.5 U6.6 U6.7 U7.1 U7.2 U7.3 U7.4 U7.5 U7.6 U7.12 U7.13
copper on no net:
  other v1: 5153.91,3258.1 4453.91,3262.73 4553.9,3262.73 4663.58,3262.73 5253.91,3262.73 5353.91,3262.73 4663.58,3426.37 5153.91,3426.37 5253.91,3426.37 5353.91,3426.37 4453.91,3426.79 4553.9,3426.79 1460.5,3588.78 1530,3588.78 5353.91,3601.04 5153.91,3602.54 5253.91,3602.54 4553.9,3614.15 4663.58,3614.15 4453.91,3616.04 1460.5,3651.76 1530,3651.55 1460.5,3720 1530,3720 3397.69,3790 3460.45,3790 3528.91,3790 2028.78,3800 2091.55,3800 2160,3800 3397.69,3859.5 3460.66,3859.5 3528.91,3859.5 2028.78,3869.5 2091.76,3869.5 2160,3869.5 3253.91,3982.01 3316.67,3982.01 3385.12,3982.01 5053.91,4045.65 3253.91,4051.51 3316.88,4051.51 3385.12,4051.51 5153.91,4051.51 5253.91,4051.51

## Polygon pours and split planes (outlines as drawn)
GND on Top Layer "GND_TOP" (solid, remove dead copper, pour order 4): 1250,2660 1250,2640 6060,2640 6060,4410 1250,4410 1250,2640
GND on Bottom Layer "GND_BOTTOM" (solid, remove dead copper, pour order 5): 1250,2660 1250,2640 6060,2640 6060,4410 1250,4410 1250,2640

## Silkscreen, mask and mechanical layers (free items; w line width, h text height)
Top Overlay:
  text "BANDPASS" at 2453.91,4286.04 h60
  text "VARIABLE GAIN & ADC" at 3921.62,4286.04 h60
  text "SCHMITT" at 5501.74,4286.04 h60
  text "Gain Adj" at 4028.91,3786.04 h60
  text "ADC Thresh" at 4603.91,3784.07 h60
  text "Sensitivity" at 5378.91,3784.07 h60
  text "5" at 3515.6,2810 h47.24 r45
  text "I" at 2860,2800 h47.24
  text "12" at 3095.49,2800 h47.24 r45
  text "O" at 3570.66,2800 h47.24
  text "G" at 3670,2800 h47.24
  text "12" at 3310,2790 h47.24 r45
  text "-5" at 3400,2780.53 h47.24 r45
  text "-12" at 2958.19,2770 h47.24 r45
  text "-12" at 3180,2770 h47.24 r45
Bottom Overlay:
  drawing of 8823 lines, arcs and shapes, not listed
  text "Patrick Barnes" at 3200,3240 h80
  text "John Lund / Rev: / Date:" at 3205.36,2850 h80
Drill Drawing:
  lines w10: 1250,2650 6050,2650 3000,2650 ; 1225,2625 1225,4425 6075,4425 6075,2625 1225,2625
